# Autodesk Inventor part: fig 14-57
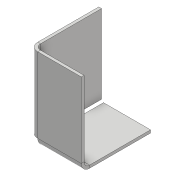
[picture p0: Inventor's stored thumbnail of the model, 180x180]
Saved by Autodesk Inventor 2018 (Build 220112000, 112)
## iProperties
Created: 2017-05
Part Number: fig 14-57
Material: Generic
Document SubType Name: Sheet Metal
Designer: CADCIM 00
Density: 1 g/cm^3
Sheet Metal Rule: Default_mm
Appearance: Default
Author: CADCIM 00
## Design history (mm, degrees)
node "Face1"
  sketch "Sketch1"
    geometry: L1 (0, 0)-(-15.678, 0); L2 (-15.678, 0)-(-15.678, -27.036); L3 (-15.678, -27.036)-(0, -27.036); L4 (0, -27.036)-(0, 0)
    constraints: 8 end point, 2 parallel, 1 horizontal, 1 perpendicular
node "Flange1"
body "Solid1"
face "Plate1" dims "d0" = 1 (= Thickness)
sketch "Sketch2"
  geometry: L1 through (0, -13.518) direction (0, 1); L2 through (-11, 0) direction (-1, 0); L3 (-22, 0)-(-22, -27.036); L4 (-22, -27.036)-(0, -27.036)
  constraints: 6 end point, 1 horizontal, 1 perpendicular, 1 vertical
face "Plate2" dims "d0" = 1 (= Thickness), "d1" = 1 (= BendReliefWidth), "d2" = 0.5 (= BendReliefDepth), "d3" = 2 (= MinimumRemnant), "d4" = 2 (= TransitionRadius), "d5" = 25, "d6" = 90 deg, "d7" = 2 (= BendRadius), "d8" = 4 (= CornerReliefSize), "d9" = 1 (= GapSize), "d10" = 2 (= JacobiRadiusSize), "SeamGap" = 0.01
bend "Bend1" dims "d0" = 1 (= Thickness), "d1" = 1 (= BendReliefWidth), "d2" = 0.5 (= BendReliefDepth), "d3" = 2 (= MinimumRemnant), "d4" = 2 (= TransitionRadius), "d5" = 25, "d6" = 90 deg, "d7" = 2 (= BendRadius), "SeamGap" = 0.01
feature "Corner1" dims "d5" = 25, "d6" = 90 deg, "d8" = 4 (= CornerReliefSize), "d9" = 1 (= GapSize), "d10" = 2 (= JacobiRadiusSize)
other parameters: "Thickness" = 1 (derived), "BendRadius" = 2 (= 2 x Thickness), "BendReliefWidth" = 1 (= Thickness), "BendReliefDepth" = 0.5 (= 0.5 x Thickness), "CornerReliefSize" = 4 (= 4 x Thickness), "MinimumRemnant" = 2 (= 2 x Thickness), "TransitionRadius" = 2 (= BendRadius), "JacobiRadiusSize" = 2 (= BendRadius), "GapSize" = 1 (= Thickness)
